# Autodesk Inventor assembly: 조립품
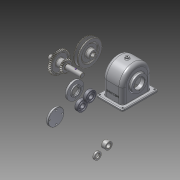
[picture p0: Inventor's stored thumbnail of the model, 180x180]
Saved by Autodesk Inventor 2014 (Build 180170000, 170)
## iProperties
Created: 2016-01
Part Number: 조립품
Document SubType Name: Assembly
Designer: user
Author: user
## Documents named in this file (11)
- C:\Users\user\Desktop\460106V1005\조립품.iam
- C:\Users\user\Desktop\460106V1005\본체.ipt
- C:\Users\user\Desktop\460106V1005\축.ipt
- C:\Users\user\Desktop\460106V1005\V-벨트풀리.ipt
- C:\Users\user\Desktop\460106V1005\뒤커버.ipt
- C:\Users\user\Desktop\460106V1005\앞커버.ipt
- C:\Users\user\Desktop\460106V1005\부시1.ipt
- C:\Users\user\Desktop\460106V1005\부시2.ipt
- C:\Users\user\Desktop\460106V1005\스퍼기어.ipt
- C:\Users\user\Desktop\460106V1005\키 - 6 x 6 x 22.ipt
- C:\Users\user\Desktop\460106V1005\베어링 6203.ipt
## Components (1 placed, 1 different names)
1. V-벨트풀리:1
